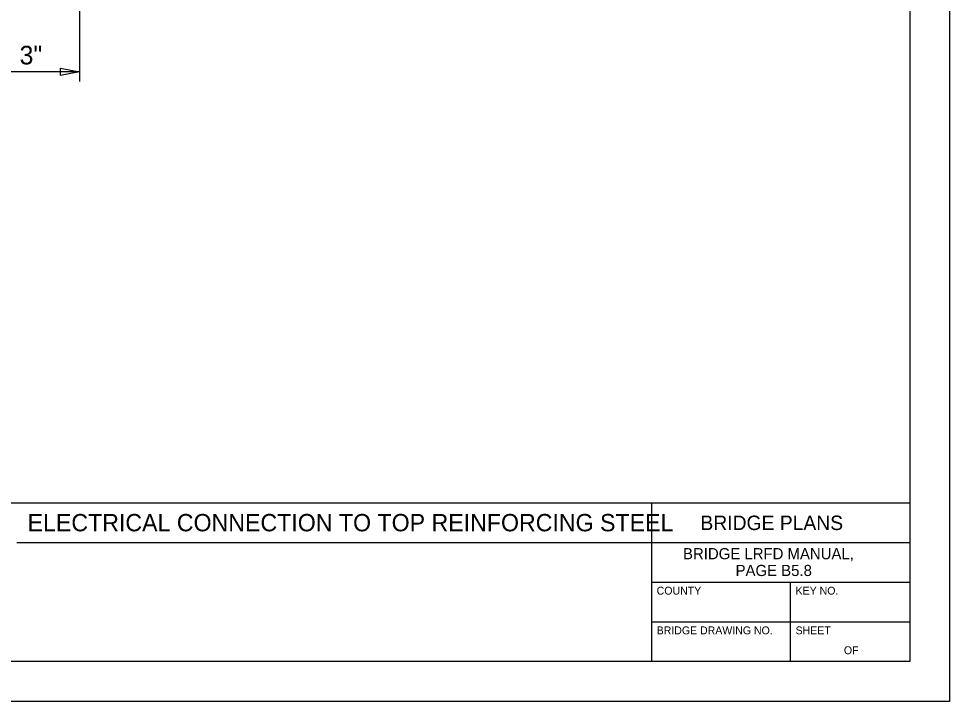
# Model space of a CAD drawing. Extents: x 0 to 2.83, y 0 to 1.96.
# Drawn here: x 1.856 to 2.833, y 0 to 0.716 of the extents above; entities that cross this region are included whole.
import ezdxf

# ---------------------------------------------------------------- set-up
doc = ezdxf.new("R2010")
doc.units = 0
for name, color, linetype in [('BORDER_ANNO_Cutsheet', 7, 'Continuous'), ('BRDG_ANNO_Anno-Sheet', 7, 'Continuous'), ('BRDG_ANNO_General-Notes', 7, 'Continuous')]:
    doc.layers.add(name, color=color, linetype=linetype)

msp = doc.modelspace()

# ---------------------------------------------------------------- linework, layer by layer
at = {"layer": 'BORDER_ANNO_Cutsheet'}
msp.add_lwpolyline([(0, 1.83333), (2.83333, 1.83333), (2.83333, 0), (0, 0)], close=True, dxfattribs=at)
at = {"layer": 'BRDG_ANNO_Anno-Sheet'}
for p, q in [((1.60417, 0.20833), (2.79167, 0.20833)), ((2.52083, 0.04167), (2.52083, 0.20833)), ((1.85417, 0.16667), (2.52083, 0.16667)), ((2.52083, 0.16667), (2.79167, 0.16667)), ((2.52083, 0.125), (2.79167, 0.125)), ((2.66667, 0.04167), (2.66667, 0.125)), ((2.52083, 0.08333), (2.79167, 0.08333))]:
    msp.add_line(p, q, dxfattribs=at)
msp.add_lwpolyline([(0.125, 1.79167), (2.79167, 1.79167), (2.79167, 0.04167), (0.125, 0.04167)], close=True, dxfattribs=at)
at = {"layer": 'BRDG_ANNO_General-Notes'}
for p, q in [((1.9201, 0.84146), (1.9201, 0.65031)), ((1.9201, 0.66031), (1.8001, 0.66031)), ((1.9001, 0.65656), (1.9001, 0.66406)), ((1.9001, 0.66406), (1.9201, 0.66031)), ((1.9201, 0.66031), (1.9001, 0.65656))]:
    msp.add_line(p, q, dxfattribs=at)

# ---------------------------------------------------------------- texts
at = {"layer": 'BRDG_ANNO_Anno-Sheet'}
for s, height, p in [('ELECTRICAL CONNECTION TO TOP REINFORCING STEEL', 0.0181772, (1.8656, 0.17839)), ('BRIDGE PLANS', 0.0151562, (2.57196, 0.17969)), ('BRIDGE LRFD MANUAL,', 0.0117188, (2.5537, 0.14904)), ('PAGE B5.8', 0.011719, (2.60887, 0.13146)), ('COUNTY', 0.008281, (2.52604, 0.11198)), ('KEY NO.', 0.008281, (2.67188, 0.11198)), ('BRIDGE DRAWING NO.', 0.0082813, (2.52604, 0.07031)), ('SHEET', 0.008281, (2.67188, 0.07031)), ('OF', 0.008281, (2.72259, 0.04948))]:
    msp.add_text(s, height=height, dxfattribs=at).set_placement(p)
at = {"layer": 'BRDG_ANNO_General-Notes'}
msp.add_text('3"', height=0.019531, dxfattribs=at).set_placement((1.85719, 0.66812))

doc.saveas('drawing.dxf')
